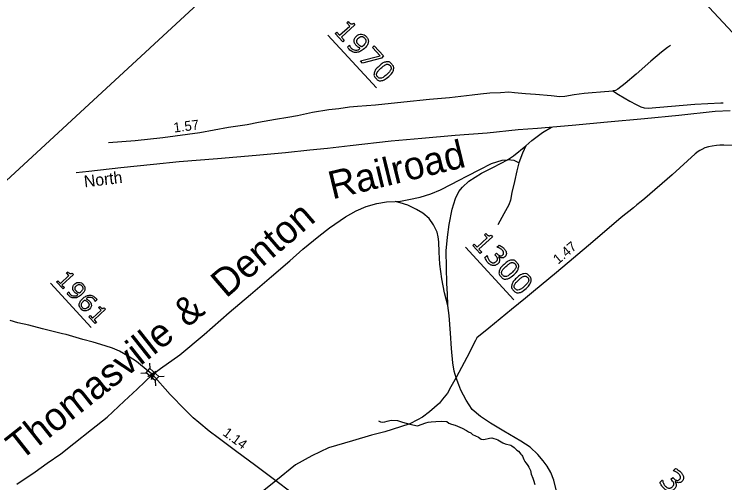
# Model space of a CAD drawing. Extents: x 1695041 to 1706254, y 786537 to 798223.
# Drawn here: x 1702938.6 to 1703356.2, y 797134.4 to 797409.7 of the extents above; entities that cross this region are included whole.
import ezdxf

# ---------------------------------------------------------------- set-up
doc = ezdxf.new("R2010")
doc.units = 0
for name, color, linetype in [('Default', 7, 'Continuous'), ('Old_Level_13', 7, 'Continuous'), ('Old_Level_30', 7, 'Continuous'), ('Old_Level_32', 7, 'Continuous')]:
    doc.layers.add(name, color=color, linetype=linetype)

msp = doc.modelspace()

# ---------------------------------------------------------------- linework, layer by layer
at = {"layer": 'Default'}
for p, q in [((1703835.77, 796884.26), (1703207.65, 797564.73)), ((1703122.9, 797397.38), (1703151.43, 797366.47)), ((1703203.76, 797272.86), (1703232.29, 797241.95)), ((1702959.81, 797251.61), (1702983.73, 797225.69)), ((1703018.08, 797204.69), (1703018.3, 797201.51)), ((1703012.98, 797198.83), (1703016.16, 797199.05)), ((1703021.47, 797194.51), (1703021.69, 797191.33)), ((1703023.56, 797196.92), (1703026.74, 797197.14))]:
    msp.add_line(p, q, dxfattribs=at)
for points in [[(1703207.65, 797564.73), (1702636.99, 797037.98), (1703265.12, 796357.5), (1703835.77, 796884.26)], [(1703131.66, 797393.56), (1703127.25, 797398.33), (1703128.15, 797399.17), (1703129.85, 797397.33), (1703135.76, 797402.79), (1703134.06, 797404.63), (1703134.87, 797405.37)], [(1703138, 797404.45), (1703138.85, 797403.53), (1703130.9, 797396.19), (1703132.56, 797394.39), (1703131.66, 797393.56)], [(1703134.48, 797390.43), (1703135.62, 797391.48), (1703135.68, 797391.42)], [(1703154.42, 797383.97), (1703143.23, 797381.02), (1703142.05, 797382.29), (1703153.75, 797385.25), (1703149.12, 797390.26), (1703150.16, 797391.22), (1703155.73, 797385.18), (1703154.42, 797383.97)], [(1703239.34, 797332.46), (1703237.25, 797328.17), (1703235.21, 797322.43)], [(1703235.21, 797322.43), (1703232.46, 797323.67), (1703228.57, 797324.25)], [(1703235.21, 797322.43), (1703233.95, 797317.78), (1703232.57, 797311.5), (1703231.07, 797304.89), (1703230.28, 797300.54), (1703229.31, 797297.78), (1703226.32, 797292.42), (1703222.88, 797285.9)], [(1703212.51, 797269.04), (1703208.1, 797273.81), (1703209, 797274.65), (1703210.7, 797272.81), (1703216.61, 797278.27), (1703214.92, 797280.11), (1703215.72, 797280.85)], [(1703218.85, 797279.93), (1703219.7, 797279.01), (1703211.75, 797271.67), (1703213.41, 797269.87), (1703212.51, 797269.04)], [(1703222.38, 797272.83), (1703222.33, 797272.89), (1703223.56, 797274.03)], [(1703221.55, 797267.88), (1703221.06, 797268.41), (1703222.04, 797269.31), (1703222.42, 797268.9)], [(1703215.24, 797266.82), (1703216.48, 797267.96), (1703216.56, 797267.87)], [(1703223.37, 797267.12), (1703223.29, 797267.05)], [(1702967.27, 797248.35), (1702963.51, 797252.42), (1702964.28, 797253.13), (1702965.73, 797251.56), (1702970.76, 797256.22), (1702969.32, 797257.78), (1702970.01, 797258.41)], [(1702972.67, 797257.63), (1702973.4, 797256.85), (1702966.62, 797250.59), (1702968.04, 797249.06), (1702967.27, 797248.35)], [(1702969.68, 797245.68), (1702970.65, 797246.58), (1702970.69, 797246.53)], [(1702987.21, 797241.88), (1702986.24, 797240.98), (1702986.2, 797241.03)], [(1702986.14, 797227.91), (1702982.38, 797231.98), (1702983.15, 797232.69), (1702984.59, 797231.12), (1702989.63, 797235.78), (1702988.19, 797237.34), (1702988.87, 797237.97)], [(1702991.54, 797237.19), (1702992.26, 797236.41), (1702985.49, 797230.16), (1702986.9, 797228.62), (1702986.14, 797227.91)], [(1703326.01, 797141.39), (1703325.95, 797141.45), (1703327.31, 797142.71)], [(1703318.16, 797134.78), (1703319.52, 797136.03), (1703319.61, 797135.93)], [(1703325.1, 797135.94), (1703324.55, 797136.53), (1703325.63, 797137.52), (1703326.05, 797137.06)], [(1703327.1, 797135.11), (1703327.01, 797135.03)]]:
    msp.add_lwpolyline(points, dxfattribs=at)
for points in [[(1703018.3, 797201.51), (1703023.57, 797196.93), (1703021.43, 797194.47), (1703016.16, 797199.05)], [(1703017.04, 797196.93), (1703021.73, 797200.05), (1703019.23, 797195), (1703019.87, 797197.94)]]:
    msp.add_lwpolyline(points, close=True, dxfattribs=at)
for points in [[(1703134.87, 797405.37), (1703135.22, 797405), (1703135.67, 797404.63), (1703136.13, 797404.26), (1703136.45, 797404.15), (1703136.85, 797404.01), (1703137.22, 797404.07), (1703137.59, 797404.12), (1703138, 797404.45)], [(1703135.68, 797391.42), (1703135.74, 797391.16), (1703135.95, 797390.77), (1703136.16, 797390.39), (1703136.52, 797390), (1703137.72, 797388.69), (1703139.2, 797388.67), (1703140.67, 797388.66), (1703142.16, 797389.81), (1703141.32, 797390.06), (1703140.73, 797390.41), (1703140.14, 797390.76), (1703139.61, 797391.34), (1703139.1, 797391.88), (1703138.8, 797392.42), (1703138.5, 797392.96), (1703138.4, 797393.69), (1703138.28, 797394.54), (1703138.6, 797395.32), (1703138.91, 797396.1), (1703139.69, 797396.82), (1703141.04, 797398.07), (1703142.71, 797397.96), (1703144.38, 797397.86), (1703145.56, 797396.58), (1703146.15, 797395.94), (1703146.46, 797395.21), (1703146.76, 797394.48), (1703146.74, 797393.7), (1703146.71, 797392.75), (1703146.19, 797391.76), (1703145.67, 797390.77), (1703144.44, 797389.64)], [(1703143.59, 797391.08), (1703144.51, 797391.93), (1703144.89, 797392.63), (1703145.27, 797393.34), (1703145.28, 797393.95), (1703145.29, 797394.48), (1703145.11, 797394.9), (1703144.93, 797395.33), (1703144.58, 797395.7), (1703143.8, 797396.55), (1703142.81, 797396.55), (1703141.82, 797396.56), (1703140.85, 797395.66), (1703140.29, 797395.14), (1703140.08, 797394.66), (1703139.87, 797394.17), (1703139.96, 797393.54), (1703140.02, 797393.11), (1703140.25, 797392.73), (1703140.48, 797392.35), (1703140.84, 797391.96), (1703141.27, 797391.5), (1703141.83, 797391.14), (1703142.39, 797390.78), (1703143.01, 797390.59), (1703143.14, 797390.7), (1703143.27, 797390.8), (1703143.4, 797390.9), (1703143.59, 797391.08)], [(1703144.44, 797389.64), (1703143.28, 797388.57), (1703142.1, 797387.96), (1703140.91, 797387.36), (1703139.75, 797387.28), (1703138.58, 797387.19), (1703137.46, 797387.66), (1703136.34, 797388.14), (1703135.33, 797389.23), (1703135.05, 797389.54), (1703134.83, 797389.84), (1703134.61, 797390.15), (1703134.48, 797390.43)], [(1703158.68, 797373.15), (1703156.3, 797370.96), (1703154.5, 797370.67), (1703152.7, 797370.39), (1703151.26, 797371.95), (1703149.79, 797373.54), (1703150.24, 797375.31), (1703150.69, 797377.08), (1703153.03, 797379.24), (1703155.39, 797381.42), (1703157.2, 797381.72), (1703159.01, 797382.01), (1703160.46, 797380.44), (1703161.92, 797378.86), (1703161.45, 797377.07), (1703160.99, 797375.28), (1703158.68, 797373.15)], [(1703154.54, 797372.22), (1703155.22, 797372.46), (1703155.93, 797372.99), (1703156.65, 797373.51), (1703157.57, 797374.36), (1703158.47, 797375.19), (1703159.07, 797375.88), (1703159.66, 797376.56), (1703159.93, 797377.2), (1703160.19, 797377.83), (1703160.09, 797378.4), (1703159.99, 797378.98), (1703159.48, 797379.54), (1703158.96, 797380.1), (1703158.39, 797380.25), (1703157.83, 797380.4), (1703157.16, 797380.18), (1703156.54, 797379.97), (1703155.76, 797379.4), (1703154.99, 797378.82), (1703154.14, 797378.04), (1703153.22, 797377.19), (1703152.65, 797376.55), (1703152.09, 797375.9), (1703151.8, 797375.24), (1703151.51, 797374.61), (1703151.6, 797374.03), (1703151.69, 797373.45), (1703152.24, 797372.86), (1703152.75, 797372.3), (1703153.32, 797372.15), (1703153.89, 797371.99), (1703154.54, 797372.22)], [(1703215.72, 797280.85), (1703216.07, 797280.48), (1703216.53, 797280.11), (1703216.98, 797279.74), (1703217.3, 797279.63), (1703217.7, 797279.49), (1703218.08, 797279.55), (1703218.45, 797279.6), (1703218.85, 797279.93)], [(1703222.42, 797268.9), (1703223.25, 797268), (1703224.13, 797267.81), (1703225, 797267.62), (1703225.72, 797268.29), (1703226.04, 797268.58), (1703226.16, 797268.94), (1703226.27, 797269.3), (1703226.2, 797269.69), (1703226.12, 797270.09), (1703225.91, 797270.43), (1703225.7, 797270.78), (1703225.36, 797271.14), (1703224.84, 797271.71), (1703224.06, 797272.16), (1703223.27, 797272.61), (1703222.38, 797272.83)], [(1703223.56, 797274.03), (1703224.16, 797273.8), (1703224.98, 797273.26), (1703225.81, 797272.72), (1703226.41, 797272.06), (1703227.01, 797271.41), (1703227.35, 797270.81), (1703227.68, 797270.21), (1703227.79, 797269.57), (1703227.9, 797268.88), (1703227.7, 797268.29), (1703227.5, 797267.7), (1703226.96, 797267.2), (1703226.22, 797266.52), (1703225.19, 797266.53), (1703224.17, 797266.55), (1703223.37, 797267.12)], [(1703223.89, 797265.24), (1703223.9, 797264.72), (1703223.68, 797264.18), (1703223.46, 797263.64), (1703222.85, 797263.08), (1703222.25, 797262.52), (1703221.54, 797262.27), (1703220.83, 797262.03), (1703220.09, 797262.08), (1703219.27, 797262.14), (1703218.51, 797262.56), (1703217.76, 797262.98), (1703217.1, 797263.69), (1703216.42, 797264.43), (1703215.94, 797265.3), (1703215.46, 797266.17), (1703215.24, 797266.82)], [(1703216.56, 797267.87), (1703216.7, 797267.06), (1703217.11, 797266.18), (1703217.52, 797265.29), (1703218.1, 797264.66), (1703218.45, 797264.28), (1703218.96, 797263.98), (1703219.48, 797263.67), (1703219.96, 797263.64), (1703220.47, 797263.6), (1703220.91, 797263.76), (1703221.35, 797263.92), (1703221.83, 797264.36), (1703222.31, 797264.8), (1703222.48, 797265.24), (1703222.65, 797265.68), (1703222.58, 797266.11), (1703222.52, 797266.55), (1703222.24, 797266.99), (1703221.96, 797267.44), (1703221.55, 797267.88)], [(1703223.29, 797267.05), (1703223.5, 797266.72), (1703223.69, 797266.21), (1703223.88, 797265.7), (1703223.89, 797265.24)], [(1703232.15, 797256.63), (1703229.77, 797254.43), (1703227.97, 797254.15), (1703226.17, 797253.87), (1703224.73, 797255.43), (1703223.26, 797257.02), (1703223.71, 797258.79), (1703224.17, 797260.56), (1703226.5, 797262.72), (1703228.86, 797264.9), (1703230.67, 797265.19), (1703232.48, 797265.49), (1703233.93, 797263.92), (1703235.39, 797262.33), (1703234.92, 797260.55), (1703234.46, 797258.76), (1703232.15, 797256.63)], [(1703228.02, 797255.7), (1703228.69, 797255.94), (1703229.41, 797256.46), (1703230.12, 797256.99), (1703231.04, 797257.83), (1703231.94, 797258.67), (1703232.54, 797259.35), (1703233.13, 797260.04), (1703233.4, 797260.68), (1703233.66, 797261.31), (1703233.56, 797261.88), (1703233.47, 797262.45), (1703232.95, 797263.02), (1703232.43, 797263.57), (1703231.86, 797263.72), (1703231.3, 797263.88), (1703230.63, 797263.66), (1703230.01, 797263.45), (1703229.23, 797262.87), (1703228.46, 797262.3), (1703227.61, 797261.52), (1703226.69, 797260.66), (1703226.13, 797260.02), (1703225.56, 797259.38), (1703225.27, 797258.72), (1703224.98, 797258.09), (1703225.07, 797257.51), (1703225.16, 797256.93), (1703225.71, 797256.33), (1703226.22, 797255.78), (1703226.79, 797255.62), (1703227.36, 797255.47), (1703228.02, 797255.7)], [(1702970.01, 797258.41), (1702970.3, 797258.1), (1702970.69, 797257.78), (1702971.08, 797257.47), (1702971.35, 797257.37), (1702971.69, 797257.26), (1702972.01, 797257.3), (1702972.33, 797257.35), (1702972.67, 797257.63)], [(1703239.53, 797248.63), (1703237.15, 797246.44), (1703235.35, 797246.15), (1703233.55, 797245.87), (1703232.11, 797247.43), (1703230.64, 797249.02), (1703231.1, 797250.79), (1703231.55, 797252.56), (1703233.89, 797254.72), (1703236.24, 797256.9), (1703238.05, 797257.2), (1703239.86, 797257.49), (1703241.31, 797255.92), (1703242.77, 797254.34), (1703242.31, 797252.55), (1703241.84, 797250.76), (1703239.53, 797248.63)], [(1702970.69, 797246.53), (1702970.75, 797246.31), (1702970.93, 797245.98), (1702971.11, 797245.65), (1702971.41, 797245.32), (1702972.44, 797244.21), (1702973.69, 797244.19), (1702974.94, 797244.18), (1702976.21, 797245.16), (1702975.5, 797245.37), (1702974.99, 797245.67), (1702974.49, 797245.97), (1702974.04, 797246.46), (1702973.61, 797246.92), (1702973.36, 797247.38), (1702973.1, 797247.84), (1702973.01, 797248.46), (1702972.91, 797249.19), (1702973.18, 797249.86), (1702973.45, 797250.52), (1702974.11, 797251.13), (1702975.26, 797252.19), (1702976.69, 797252.1), (1702978.11, 797252.01), (1702979.11, 797250.92), (1702979.62, 797250.38), (1702979.88, 797249.76), (1702980.14, 797249.14), (1702980.12, 797248.48), (1702980.1, 797247.66), (1702979.65, 797246.82), (1702979.21, 797245.98), (1702978.16, 797245.01)], [(1703235.4, 797247.7), (1703236.07, 797247.94), (1703236.79, 797248.47), (1703237.51, 797248.99), (1703238.42, 797249.84), (1703239.32, 797250.67), (1703239.92, 797251.36), (1703240.52, 797252.04), (1703240.78, 797252.68), (1703241.05, 797253.31), (1703240.95, 797253.88), (1703240.85, 797254.46), (1703240.33, 797255.02), (1703239.81, 797255.58), (1703239.25, 797255.73), (1703238.68, 797255.88), (1703238.01, 797255.66), (1703237.39, 797255.45), (1703236.61, 797254.88), (1703235.84, 797254.3), (1703235, 797253.52), (1703234.07, 797252.67), (1703233.51, 797252.03), (1703232.95, 797251.38), (1703232.65, 797250.72), (1703232.37, 797250.09), (1703232.45, 797249.51), (1703232.54, 797248.93), (1703233.09, 797248.34), (1703233.6, 797247.78), (1703234.17, 797247.63), (1703234.74, 797247.47), (1703235.4, 797247.7)], [(1702977.43, 797246.24), (1702978.22, 797246.96), (1702978.54, 797247.56), (1702978.87, 797248.16), (1702978.87, 797248.69), (1702978.88, 797249.13), (1702978.73, 797249.5), (1702978.57, 797249.86), (1702978.28, 797250.18), (1702977.61, 797250.9), (1702976.77, 797250.9), (1702975.92, 797250.91), (1702975.1, 797250.15), (1702974.62, 797249.7), (1702974.44, 797249.29), (1702974.27, 797248.87), (1702974.34, 797248.34), (1702974.39, 797247.97), (1702974.59, 797247.65), (1702974.79, 797247.33), (1702975.09, 797246.99), (1702975.46, 797246.6), (1702975.93, 797246.29), (1702976.41, 797245.99), (1702976.94, 797245.82), (1702977.05, 797245.92), (1702977.16, 797246), (1702977.27, 797246.09), (1702977.43, 797246.24)], [(1702978.16, 797245.01), (1702977.17, 797244.1), (1702976.16, 797243.59), (1702975.15, 797243.07), (1702974.17, 797243), (1702973.17, 797242.93), (1702972.21, 797243.33), (1702971.26, 797243.73), (1702970.4, 797244.67), (1702970.16, 797244.93), (1702969.97, 797245.19), (1702969.78, 797245.45), (1702969.68, 797245.68)], [(1702982.78, 797236.43), (1702981.64, 797235.38), (1702980.21, 797235.46), (1702978.79, 797235.55), (1702977.78, 797236.64), (1702977.27, 797237.2), (1702977.02, 797237.81), (1702976.77, 797238.42), (1702976.79, 797239.09), (1702976.81, 797239.91), (1702977.29, 797240.78), (1702977.76, 797241.65), (1702978.74, 797242.55), (1702979.74, 797243.48), (1702980.71, 797243.97), (1702981.68, 797244.47), (1702982.71, 797244.56), (1702983.69, 797244.64), (1702984.66, 797244.24), (1702985.63, 797243.83), (1702986.49, 797242.89), (1702986.77, 797242.6), (1702986.93, 797242.37), (1702987.09, 797242.15), (1702987.21, 797241.88)], [(1702981.79, 797237.42), (1702982.26, 797237.85), (1702982.44, 797238.27), (1702982.62, 797238.7), (1702982.55, 797239.22), (1702982.5, 797239.6), (1702982.29, 797239.93), (1702982.08, 797240.26), (1702981.8, 797240.57), (1702981.4, 797241), (1702980.96, 797241.27), (1702980.52, 797241.55), (1702979.95, 797241.74), (1702979.83, 797241.65), (1702979.72, 797241.56), (1702979.61, 797241.47), (1702979.46, 797241.32), (1702978.66, 797240.59), (1702978.35, 797240), (1702978.04, 797239.41), (1702978.04, 797238.87), (1702978.03, 797238.44), (1702978.18, 797238.07), (1702978.32, 797237.71), (1702978.62, 797237.39), (1702979.29, 797236.66), (1702980.12, 797236.65), (1702980.96, 797236.65), (1702981.79, 797237.42)], [(1702986.2, 797241.03), (1702986.14, 797241.25), (1702985.95, 797241.59), (1702985.76, 797241.94), (1702985.48, 797242.24), (1702984.48, 797243.32), (1702983.21, 797243.34), (1702981.93, 797243.36), (1702980.68, 797242.4), (1702981.33, 797242.22), (1702981.84, 797241.93), (1702982.35, 797241.64), (1702982.85, 797241.1), (1702983.29, 797240.62), (1702983.54, 797240.18), (1702983.79, 797239.73), (1702983.88, 797239.1), (1702983.98, 797238.37), (1702983.72, 797237.71), (1702983.45, 797237.05), (1702982.78, 797236.43)], [(1702988.87, 797237.97), (1702989.17, 797237.66), (1702989.56, 797237.34), (1702989.94, 797237.03), (1702990.22, 797236.93), (1702990.56, 797236.82), (1702990.88, 797236.86), (1702991.19, 797236.91), (1702991.54, 797237.19)], [(1703326.05, 797137.06), (1703326.97, 797136.07), (1703327.93, 797135.86), (1703328.89, 797135.66), (1703329.69, 797136.39), (1703330.04, 797136.72), (1703330.16, 797137.11), (1703330.29, 797137.51), (1703330.21, 797137.93), (1703330.12, 797138.37), (1703329.89, 797138.75), (1703329.66, 797139.13), (1703329.29, 797139.53), (1703328.72, 797140.15), (1703327.85, 797140.65), (1703326.99, 797141.14), (1703326.01, 797141.39)], [(1703327.31, 797142.71), (1703327.96, 797142.46), (1703328.87, 797141.86), (1703329.78, 797141.26), (1703330.45, 797140.54), (1703331.1, 797139.83), (1703331.47, 797139.17), (1703331.84, 797138.5), (1703331.96, 797137.8), (1703332.08, 797137.04), (1703331.86, 797136.39), (1703331.64, 797135.74), (1703331.04, 797135.19), (1703330.23, 797134.45), (1703329.1, 797134.46), (1703327.97, 797134.48), (1703327.1, 797135.11)], [(1703319.61, 797135.93), (1703319.76, 797135.04), (1703320.21, 797134.07), (1703320.66, 797133.1), (1703321.3, 797132.4), (1703321.68, 797131.99), (1703322.25, 797131.65), (1703322.81, 797131.31), (1703323.35, 797131.27), (1703323.91, 797131.24), (1703324.39, 797131.41), (1703324.88, 797131.58), (1703325.41, 797132.07), (1703325.93, 797132.56), (1703326.12, 797133.04), (1703326.31, 797133.52), (1703326.23, 797134), (1703326.16, 797134.48), (1703325.85, 797134.97), (1703325.54, 797135.45), (1703325.1, 797135.94)], [(1703327.01, 797135.03), (1703327.24, 797134.66), (1703327.45, 797134.11), (1703327.66, 797133.55), (1703327.67, 797133.04)], [(1703327.67, 797133.04), (1703327.68, 797132.47), (1703327.44, 797131.87), (1703327.2, 797131.28), (1703326.53, 797130.66), (1703325.86, 797130.04), (1703325.09, 797129.77), (1703324.31, 797129.5), (1703323.49, 797129.56), (1703322.59, 797129.63), (1703321.76, 797130.09), (1703320.93, 797130.55), (1703320.2, 797131.34), (1703319.45, 797132.14), (1703318.92, 797133.1), (1703318.39, 797134.06), (1703318.16, 797134.78)]]:
    msp.add_open_spline(points, degree=3, dxfattribs=at)
at = {"layer": 'Old_Level_13'}
for points in [[(1702974.97, 797316.73), (1702982.4, 797317.52), (1703001.26, 797319.73), (1703020.51, 797321.65), (1703035.57, 797323.26), (1703058.15, 797324.99), (1703080.74, 797326.95), (1703098, 797328.45), (1703112.41, 797330.08), (1703122.72, 797331.11), (1703135.99, 797332.6), (1703160.19, 797335.29), (1703178.25, 797336.88), (1703197.69, 797338.61), (1703216.47, 797340.11), (1703234.88, 797342.01), (1703246.09, 797342.73), (1703266.58, 797344.56), (1703287.34, 797346.48), (1703309.13, 797348.5), (1703329.25, 797350.46), (1703350.62, 797352.68), (1703359.41, 797353.24)], [(1703239.34, 797332.46), (1703242.82, 797335.5), (1703249.12, 797340.25), (1703254.36, 797343.29)], [(1703228.57, 797324.25), (1703232, 797326.52), (1703239.34, 797332.46)], [(1703162.55, 797299.66), (1703165.7, 797299.9), (1703170.53, 797300.79), (1703177.12, 797302.2), (1703183.5, 797304.12), (1703189.16, 797306.55), (1703195.59, 797309.79), (1703199.75, 797311.96), (1703204.91, 797314.79), (1703212.34, 797318.57), (1703219.05, 797321.93), (1703225.34, 797324.06), (1703228.57, 797324.25)], [(1703193.44, 797238.63), (1703193.29, 797245.38), (1703192.85, 797251.49), (1703192.7, 797260.98), (1703192.43, 797270.75), (1703193.25, 797278.76), (1703194.25, 797286.16), (1703196.09, 797295.1), (1703198.01, 797301.36), (1703199.9, 797305.47), (1703202.12, 797308.12), (1703205.88, 797311.67), (1703213.16, 797316.3), (1703219.57, 797319.55), (1703224.87, 797322.13), (1703228.57, 797324.25)], [(1702940.21, 797133.51), (1702950.94, 797140.93), (1702957.97, 797145.85), (1702966.01, 797151.43), (1702973.54, 797157.56), (1702983.94, 797165.65), (1702993.23, 797173.02), (1703003.2, 797182.37), (1703010.85, 797189.49), (1703019.87, 797197.94), (1703024.61, 797201.54), (1703035.84, 797209.54), (1703050.25, 797221.44), (1703064.92, 797234.45), (1703077.37, 797244.94), (1703089.76, 797255.62), (1703100.59, 797264.75), (1703108.29, 797271.65), (1703117.54, 797279.34), (1703123.98, 797284.21), (1703133.29, 797290.73), (1703139.61, 797294.23), (1703145.54, 797296.64), (1703151.7, 797298.51), (1703157.49, 797299.43), (1703162.55, 797299.66)], [(1703193.44, 797238.63), (1703191.42, 797245.93), (1703189.84, 797254.23), (1703188.67, 797262.94), (1703188.4, 797269.94), (1703188.08, 797275.91), (1703187.77, 797279), (1703187.17, 797281.58), (1703185.08, 797285.94), (1703182.5, 797289.7), (1703178.84, 797292.76), (1703175.02, 797295.03), (1703169.84, 797297.43), (1703165.4, 797298.88), (1703162.55, 797299.66)], [(1703257.31, 797129.4), (1703255.71, 797135.94), (1703254.01, 797140.41), (1703251.91, 797144.24), (1703249.56, 797147.34), (1703246.26, 797151.1), (1703241.82, 797155.29), (1703236.29, 797158.88), (1703226.28, 797164.78), (1703218.59, 797169.51), (1703212.62, 797173.32), (1703207.78, 797177.53), (1703204.18, 797182.99), (1703201.17, 797188.9), (1703199.87, 797191.96), (1703198.42, 797196.02), (1703197.24, 797200.05), (1703196.34, 797204.88), (1703195.62, 797213.35), (1703195.11, 797222.28), (1703194.16, 797232.78), (1703193.44, 797238.63)]]:
    msp.add_lwpolyline(points, dxfattribs=at)
at = {"layer": 'Old_Level_30'}
msp.add_lwpolyline([(1703152.68, 797170.83), (1703153.8, 797170.27), (1703154.91, 797170.09), (1703156.41, 797170.18), (1703157.86, 797170.64), (1703159.27, 797170.98), (1703160.57, 797171.2), (1703163.77, 797171.07), (1703166.75, 797170.08), (1703171.05, 797168.75), (1703175.68, 797167.83), (1703180.44, 797169.65), (1703181.9, 797169.96), (1703183.66, 797170.25), (1703186.33, 797170.47), (1703189.84, 797170.57), (1703192.83, 797170.49), (1703194.12, 797169.36), (1703195.64, 797168.88), (1703197.81, 797168.18), (1703201.83, 797166.55), (1703204.5, 797165.09), (1703205.69, 797164.39), (1703206.9, 797163.7), (1703207.92, 797162.83), (1703211.39, 797161.14), (1703213.11, 797160.05), (1703214.53, 797159.8), (1703218.03, 797160.69), (1703219.28, 797160.8), (1703220.47, 797160.35), (1703221.95, 797159.98), (1703222.8, 797159.56), (1703225.81, 797157.96), (1703227.15, 797157.26), (1703230.47, 797156.41), (1703231.16, 797156.16), (1703232.51, 797155.21), (1703233.91, 797153.52), (1703234.9, 797152.91), (1703236.42, 797151.24), (1703236.98, 797150.59), (1703237.25, 797149.97), (1703238.03, 797148.11), (1703238.63, 797146.98), (1703239.22, 797146.06), (1703240.04, 797145.1), (1703240.47, 797144.53), (1703241.04, 797143.5), (1703241.98, 797141.52), (1703242.43, 797139.53), (1703243.31, 797137.13), (1703243.83, 797135.95), (1703244.51, 797133.4)], dxfattribs=at)
at = {"layer": 'Old_Level_32'}
for points in [[(1703324.26, 797391.32), (1703322.48, 797390.24), (1703318.96, 797387.46), (1703312.81, 797382.07), (1703304.13, 797374.48), (1703297.75, 797369.04), (1703293.43, 797365.63), (1703291.9, 797364.93), (1703290.37, 797364.62)], [(1702994.01, 797334.3), (1703009.65, 797335.58), (1703025.97, 797337.32), (1703047.66, 797340.17), (1703064.54, 797343.38), (1703075.46, 797345.01), (1703082.17, 797346.33), (1703092.07, 797348.01), (1703099.43, 797349.29), (1703105.06, 797350.22), (1703113.95, 797352.08), (1703123.55, 797353.77), (1703129.45, 797354.31), (1703135.68, 797355.29), (1703140.41, 797355.68), (1703150.84, 797356.42), (1703167.53, 797358.29), (1703182.75, 797359.87), (1703194.52, 797360.88), (1703207.7, 797362.33), (1703212.68, 797362.91), (1703218.17, 797363.47), (1703224.43, 797363.74), (1703229.27, 797364.2), (1703232.64, 797363.8), (1703239.07, 797363.22), (1703244.91, 797362.72), (1703254.19, 797361.89), (1703259.25, 797361.43), (1703262.19, 797361.64), (1703267.63, 797362.52), (1703273.59, 797363.39), (1703278.23, 797363.79), (1703283.11, 797364.12), (1703290.37, 797364.62)], [(1703290.37, 797364.62), (1703293.76, 797362.57), (1703300.39, 797358.68), (1703304.1, 797356.64), (1703306.8, 797355.29), (1703308.77, 797354.62), (1703311.13, 797354.42), (1703338.54, 797356.89), (1703353.99, 797357.65), (1703355.32, 797357.67)], [(1703372.17, 797332.53), (1703355.65, 797332.84), (1703353.39, 797332.7), (1703351.29, 797332.5), (1703348.84, 797332.22), (1703346.66, 797331.82), (1703344.51, 797331.14), (1703342.71, 797330.27), (1703341.63, 797329.71), (1703340.58, 797329.09), (1703338.74, 797327.69), (1703325.26, 797315.26), (1703309.22, 797301.35), (1703307.1, 797299.71), (1703304.59, 797297.69), (1703302.57, 797296.02), (1703295.36, 797290.19), (1703278.71, 797276.02), (1703267.37, 797266.45), (1703257.4, 797257.99), (1703243.82, 797246.8), (1703239.16, 797242.95), (1703230.88, 797236.21), (1703217.47, 797225.17), (1703210.56, 797219.54), (1703209.8, 797217.94), (1703204.59, 797208.05), (1703198.28, 797196.35)], [(1703092.31, 797135.56), (1703080.63, 797144.44), (1703068.64, 797153.19), (1703058.51, 797160.74), (1703053.22, 797164.79), (1703047.05, 797169.73), (1703043.74, 797172.51), (1703038.96, 797177.22), (1703030.32, 797186.35), (1703019.87, 797197.94), (1703018.22, 797199.27), (1703012.72, 797203.72), (1703010.37, 797205.67), (1703006.09, 797208.5), (1703000.52, 797211.76), (1702996.31, 797213.55), (1702991.97, 797214.88), (1702984.95, 797217.07), (1702978.88, 797218.59), (1702969.12, 797221.46), (1702966.91, 797221.96), (1702955.2, 797224.95), (1702947.25, 797226.92), (1702940.73, 797228.34), (1702936.13, 797229.69)], [(1703198.28, 797196.35), (1703195.27, 797190.78), (1703193.26, 797186.98), (1703190.4, 797183.44), (1703188.52, 797181.1), (1703182.72, 797176.05), (1703178.56, 797172.96), (1703175.69, 797171.36), (1703171.18, 797169.13), (1703165.66, 797167.34), (1703156.45, 797164.36), (1703148.52, 797162.28), (1703137.44, 797159.07), (1703123.38, 797155.02), (1703113.5, 797150.33), (1703103.92, 797144.96), (1703092.31, 797135.56)], [(1703092.31, 797135.56), (1703085.37, 797129.85), (1703079.87, 797125.08), (1703069.81, 797116.71), (1703049.22, 797100.27), (1703036.49, 797089.63), (1703025.26, 797080.73), (1703015.49, 797072.63), (1703014, 797071.07), (1703013.08, 797069.67), (1703010.64, 797065.27), (1703009.64, 797062.15), (1703009.3, 797058.13), (1703006.52, 797039.18), (1703005.71, 797034.38)], [(1703235.91, 797066.04), (1703231.89, 797069.38), (1703226.52, 797073.5), (1703219.83, 797079.27), (1703215.66, 797082.12), (1703208.68, 797086.93), (1703203.22, 797089.23), (1703195.35, 797092.48), (1703187.55, 797095.63), (1703177.18, 797099.09), (1703168.91, 797102.2), (1703162.03, 797105.01), (1703154.31, 797107.64), (1703151.39, 797108.53), (1703144, 797110.73), (1703129.49, 797114.72), (1703124.62, 797116.23), (1703121.95, 797117.03), (1703115.84, 797119.7), (1703113.85, 797120.64), (1703110.13, 797122.75), (1703105.95, 797125.3), (1703101.17, 797128.92), (1703092.31, 797135.56)]]:
    msp.add_lwpolyline(points, dxfattribs=at)

# ---------------------------------------------------------------- texts
at = {"layer": 'Default'}
for s, height, rotation, p in [('1.57', 5.775, 7.1609, (1703032.59, 797340.19)), ('Railroad', 16.378, 13.7134, (1703125.55, 797300.86)), ('North', 6.93, 6.6951, (1702979.97, 797307.96)), ('Denton', 16.378, 40.7509, (1703063.12, 797242.51)), ('1.47', 5.775, 40.3019, (1703258.3, 797262.55)), ('&', 16.38, 39.5489, (1703040.37, 797225.14)), ('Thomasville', 16.3775, 38.3974, (1702942.2, 797147)), ('1.14', 5.775, 323.3013, (1703060.7, 797162.71))]:
    msp.add_text(s, height=height, rotation=rotation, dxfattribs=at).set_placement(p)

doc.saveas('drawing.dxf')
